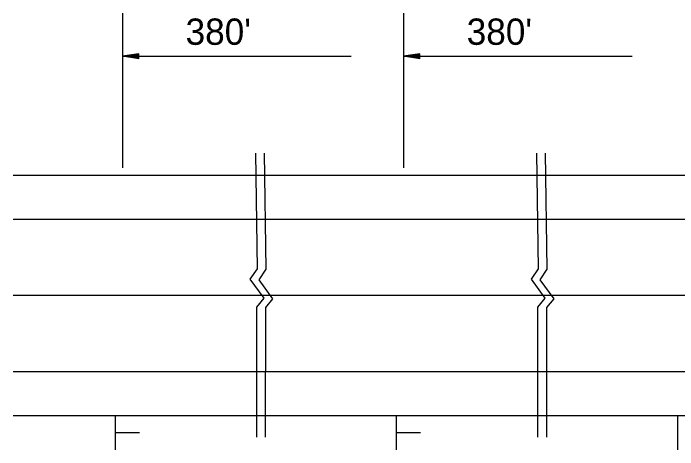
# Model space of a CAD drawing. Extents: x 1678017 to 1687792, y 404433 to 413488.
# Drawn here: x 1679931.9 to 1680083.5, y 405155.6 to 405255.1 of the extents above; entities that cross this region are included whole.
import ezdxf

# ---------------------------------------------------------------- set-up
doc = ezdxf.new("R2010")
doc.units = 0
doc.layers.add('Default', color=7, linetype='Continuous')

msp = doc.modelspace()

# ---------------------------------------------------------------- linework, layer by layer
at = {"layer": 'Default'}
for p, q in [((1679956.81, 405255.07), (1679956.81, 405219.86)), ((1680020.97, 405255.07), (1680020.97, 405219.86)), ((1679960.56, 405245.84), (1679956.81, 405245.28)), ((1679960.56, 405244.71), (1679960.56, 405245.84)), ((1680024.72, 405245.84), (1680020.97, 405245.28)), ((1680024.72, 405244.71), (1680024.72, 405245.84)), ((1679956.81, 405245.28), (1680009, 405245.28)), ((1679960.56, 405244.71), (1679956.81, 405245.28)), ((1679960.56, 405245.74), (1679957.43, 405245.28)), ((1679960.56, 405244.81), (1679957.43, 405245.28)), ((1679960.56, 405245.65), (1679958.08, 405245.28)), ((1679960.56, 405244.9), (1679958.08, 405245.28)), ((1679960.56, 405245.56), (1679958.7, 405245.28)), ((1679960.56, 405245), (1679958.7, 405245.28)), ((1679960.56, 405245.46), (1679959.34, 405245.28)), ((1679960.56, 405245.09), (1679959.34, 405245.28)), ((1679960.56, 405245.36), (1679959.96, 405245.28)), ((1679960.56, 405245.19), (1679959.96, 405245.28)), ((1680020.97, 405245.28), (1680073.16, 405245.28)), ((1680024.72, 405244.71), (1680020.97, 405245.28)), ((1680024.72, 405245.74), (1680021.59, 405245.28)), ((1680024.72, 405244.81), (1680021.59, 405245.28)), ((1680024.72, 405245.65), (1680022.24, 405245.28)), ((1680024.72, 405244.9), (1680022.24, 405245.28)), ((1680024.72, 405245.56), (1680022.86, 405245.28)), ((1680024.72, 405245), (1680022.86, 405245.28)), ((1680024.72, 405245.46), (1680023.5, 405245.28)), ((1680024.72, 405245.09), (1680023.5, 405245.28)), ((1680024.72, 405245.36), (1680024.12, 405245.28)), ((1680024.72, 405245.19), (1680024.12, 405245.28)), ((1679931.89, 405218.16), (1680990.24, 405218.16)), ((1679931.89, 405208.16), (1680480.65, 405208.16)), ((1679931.89, 405190.77), (1680368.2, 405190.77)), ((1679931.89, 405173.39), (1680480.65, 405173.39)), ((1679931.89, 405163.39), (1680990.24, 405163.39)), ((1679955.22, 405155.57), (1679955.22, 405163.39)), ((1680019.38, 405155.57), (1680019.38, 405163.39)), ((1680083.54, 405155.57), (1680083.54, 405163.39)), ((1679955.33, 405159.46), (1679960.68, 405159.46)), ((1680019.5, 405159.46), (1680024.84, 405159.46))]:
    msp.add_line(p, q, dxfattribs=at)
for points in [[(1679987.14, 405223.16), (1679987.54, 405196.83), (1679985.92, 405194.42), (1679989.08, 405190.09), (1679987.42, 405188.09), (1679987.41, 405158.39)], [(1679989.14, 405223.16), (1679989.54, 405196.75), (1679987.92, 405194.33), (1679991.08, 405190), (1679989.42, 405188), (1679989.41, 405158.39)], [(1680051.3, 405223.16), (1680051.7, 405196.83), (1680050.08, 405194.42), (1680053.24, 405190.09), (1680051.58, 405188.09), (1680051.57, 405158.39)], [(1680053.3, 405223.16), (1680053.7, 405196.75), (1680052.08, 405194.33), (1680055.24, 405190), (1680053.58, 405188), (1680053.57, 405158.39)]]:
    msp.add_lwpolyline(points, dxfattribs=at)

# ---------------------------------------------------------------- texts
for p in [(1679971.22, 405247.88), (1680035.38, 405247.88)]:
    msp.add_text("380'", height=6, dxfattribs=at).set_placement(p)

doc.saveas('drawing.dxf')
